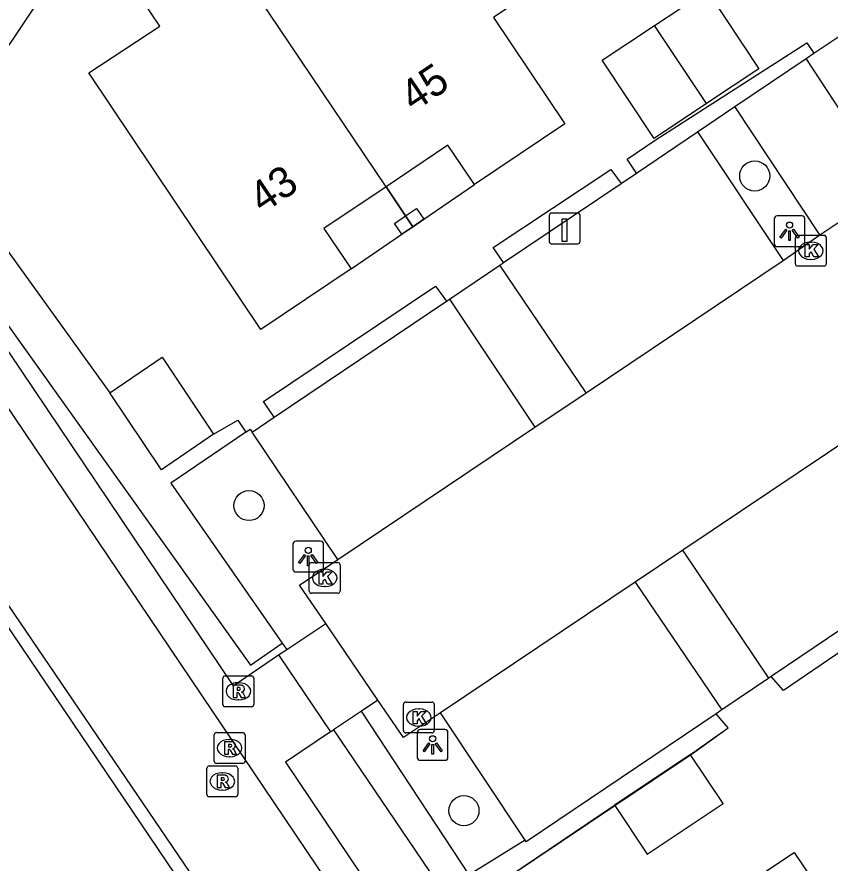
# Model space of a CAD drawing. Extents: x 158797 to 159887, y 384318 to 385255.
# Drawn here: x 158945.21 to 158971.6, y 384679.81 to 384707.27 of the extents above; entities that cross this region are included whole.
import ezdxf

# ---------------------------------------------------------------- set-up
doc = ezdxf.new("R2010")
doc.units = 0
for name, color, linetype in [('IMGEO_Berm_groen', 7, 'Continuous'), ('IMGEO_Boom', 7, 'Continuous'), ('IMGEO_Groenvoorziening', 7, 'Continuous'), ('IMGEO_Haag', 7, 'Continuous'), ('IMGEO_Kolk', 7, 'Continuous'), ('IMGEO_Laadpaal', 7, 'Continuous'), ('IMGEO_Lichtpunt', 7, 'Continuous'), ('IMGEO_Pand', 7, 'Continuous'), ('IMGEO_Pand_nummerreeks', 7, 'Continuous'), ('IMGEO_Pand_overbouw', 7, 'Continuous'), ('IMGEO_Parkeervlak_open', 7, 'Continuous'), ('IMGEO_Rijbaan_lokaal_open', 7, 'Continuous'), ('IMGEO_Rioolput', 7, 'Continuous'), ('IMGEO_Voetpad_halfverhard', 7, 'Continuous'), ('IMGEO_Voetpad_op_trap', 7, 'Continuous'), ('IMGEO_Voetpad_open', 7, 'Continuous')]:
    doc.layers.add(name, color=color, linetype=linetype)

msp = doc.modelspace()

# ---------------------------------------------------------------- linework, layer by layer
at = {"layer": 'IMGEO_Berm_groen'}
msp.add_lwpolyline([(158953.822, 384686.947), (158953.964, 384686.744)], dxfattribs=at)
at = {"layer": 'IMGEO_Boom'}
for centre in [(158969.154, 384702.11), (158952.741, 384691.413), (158959.716, 384681.512)]:
    msp.add_circle(centre, 0.489, dxfattribs=at)
at = {"layer": 'IMGEO_Groenvoorziening'}
for points in [[(158952.639, 384693.793), (158952.782, 384693.887), (158952.843, 384693.8)], [(158967.066, 384683.335), (158968.288, 384684.196)], [(158960.312, 384678.787), (158964.603, 384681.689)]]:
    msp.add_lwpolyline(points, dxfattribs=at)
at = {"layer": 'IMGEO_Haag'}
for points in [[(158966.613, 384739.202), (158965.512, 384740.522), (158941.142, 384702.551), (158952.786, 384686.235), (158953.822, 384686.947)], [(158966.078, 384738.835), (158965.491, 384739.134), (158959.225, 384729.429), (158959.613, 384729.029), (158955.43, 384722.46), (158949.45, 384713.078), (158942.598, 384702.871), (158948.229, 384695.075)], [(158965.32, 384702.204), (158965.013, 384702.659), (158965.927, 384703.267), (158970.844, 384706.429), (158971.076, 384706.091)], [(158967.298, 384703.536), (158968.504, 384704.361)], [(158961.002, 384699.296), (158960.66, 384699.787), (158964.489, 384702.315), (158964.816, 384701.864)], [(158953.553, 384694.278), (158953.207, 384694.787), (158958.791, 384698.529), (158959.147, 384698.046)], [(158951.593, 384693.727), (158952.375, 384694.187), (158952.639, 384693.793)], [(158952.639, 384693.793), (158950.206, 384692.135), (158953.822, 384686.947)], [(158977.555, 384656.193), (158970.058, 384651.22), (158941.507, 384693.215), (158927, 384683.401), (158930.702, 384677.442), (158928.077, 384675.641), (158928.67, 384674.688)], [(158982.198, 384627.503), (158986.877, 384630.783), (158991.18, 384624.297), (159005.347, 384633.805), (158997.226, 384645.658), (158986.56, 384661.35), (158977.807, 384655.577), (158970.042, 384650.292), (158941.462, 384692.581), (158927.478, 384683.208), (158931.293, 384677.308), (158928.892, 384675.59), (158929.234, 384675.051), (158928.67, 384674.688)], [(158976.326, 384689.664), (158970.085, 384685.407), (158969.689, 384685.861)], [(158961.705, 384680.553), (158959.891, 384679.427), (158956.395, 384684.743)], [(158968.288, 384684.196), (158967.901, 384684.656)], [(158955.484, 384684.134), (158959.482, 384678.23)], [(158967.07, 384683.329), (158967.131, 384683.37), (158968.288, 384684.196)], [(158964.611, 384681.677), (158967.07, 384683.329)], [(158960.312, 384678.787), (158964.611, 384681.677)]]:
    msp.add_lwpolyline(points, dxfattribs=at)
at = {"layer": 'IMGEO_Kolk'}
for p, q in [((158970.55, 384700.183), (158971.402, 384700.183)), ((158970.475, 384699.257), (158970.475, 384700.109)), ((158970.963, 384699.963), (158970.988, 384699.963)), ((158971.476, 384700.109), (158971.476, 384699.257)), ((158970.986, 384699.403), (158970.961, 384699.403)), ((158971.402, 384699.183), (158970.55, 384699.183)), ((158954.697, 384688.639), (158954.697, 384689.491)), ((158954.772, 384689.565), (158955.624, 384689.565)), ((158955.698, 384689.491), (158955.698, 384688.639)), ((158955.185, 384689.345), (158955.21, 384689.345)), ((158955.208, 384688.785), (158955.183, 384688.785)), ((158955.624, 384688.565), (158954.772, 384688.565)), ((158957.752, 384684.109), (158957.752, 384684.961)), ((158957.827, 384685.035), (158958.679, 384685.035)), ((158958.24, 384684.815), (158958.265, 384684.815)), ((158958.753, 384684.961), (158958.753, 384684.109)), ((158958.263, 384684.255), (158958.238, 384684.255)), ((158958.679, 384684.035), (158957.827, 384684.035))]:
    msp.add_line(p, q, dxfattribs=at)
for points in [[(158970.55, 384700.183), (158971.402, 384700.183)], [(158970.475, 384699.257), (158970.475, 384700.109)], [(158971.476, 384700.109), (158971.476, 384699.257)], [(158970.796, 384699.883), (158970.919, 384699.883), (158970.919, 384699.732), (158971.049, 384699.883), (158971.213, 384699.883), (158971.067, 384699.732), (158971.22, 384699.483), (158971.068, 384699.483), (158970.983, 384699.647), (158970.919, 384699.58), (158970.919, 384699.483), (158970.796, 384699.483), (158970.796, 384699.883)], [(158971.402, 384699.183), (158970.55, 384699.183)], [(158954.697, 384688.639), (158954.697, 384689.491)], [(158954.772, 384689.565), (158955.624, 384689.565)], [(158955.698, 384689.491), (158955.698, 384688.639)], [(158955.018, 384689.265), (158955.141, 384689.265), (158955.141, 384689.114), (158955.271, 384689.265), (158955.435, 384689.265), (158955.289, 384689.114), (158955.442, 384688.865), (158955.29, 384688.865), (158955.205, 384689.029), (158955.141, 384688.962), (158955.141, 384688.865), (158955.018, 384688.865), (158955.018, 384689.265)], [(158955.624, 384688.565), (158954.772, 384688.565)], [(158957.752, 384684.109), (158957.752, 384684.961)], [(158957.827, 384685.035), (158958.679, 384685.035)], [(158958.753, 384684.961), (158958.753, 384684.109)], [(158958.073, 384684.735), (158958.196, 384684.735), (158958.196, 384684.584), (158958.326, 384684.735), (158958.49, 384684.735), (158958.344, 384684.584), (158958.497, 384684.335), (158958.345, 384684.335), (158958.26, 384684.499), (158958.196, 384684.432), (158958.196, 384684.335), (158958.073, 384684.335), (158958.073, 384684.735)], [(158958.679, 384684.035), (158957.827, 384684.035)]]:
    msp.add_lwpolyline(points, dxfattribs=at)
for centre, start, end in [((158970.552, 384700.107), 91.552, 178.448), ((158970.552, 384700.107), 91.552, 178.448), ((158971.4, 384700.107), 1.552, 88.448), ((158971.4, 384700.107), 1.552, 88.448), ((158970.552, 384699.259), 181.552, 268.448), ((158970.552, 384699.259), 181.552, 268.448), ((158971.4, 384699.259), 271.552, 358.448), ((158971.4, 384699.259), 271.552, 358.448), ((158954.774, 384689.489), 91.552, 178.448), ((158954.774, 384689.489), 91.552, 178.448), ((158955.622, 384689.489), 1.552, 88.448), ((158955.622, 384689.489), 1.552, 88.448), ((158954.774, 384688.641), 181.552, 268.448), ((158954.774, 384688.641), 181.552, 268.448), ((158955.622, 384688.641), 271.552, 358.448), ((158955.622, 384688.641), 271.552, 358.448), ((158957.829, 384684.959), 91.552, 178.448), ((158957.829, 384684.959), 91.552, 178.448), ((158958.677, 384684.959), 1.552, 88.448), ((158958.677, 384684.959), 1.552, 88.448), ((158957.829, 384684.111), 181.552, 268.448), ((158957.829, 384684.111), 181.552, 268.448), ((158958.677, 384684.111), 271.552, 358.448), ((158958.677, 384684.111), 271.552, 358.448)]:
    msp.add_arc(centre, 0.0765, start, end, dxfattribs=at)
for centre, major_axis, ratio, start_param, end_param in [((158970.962, 384699.683), (-0.387, 0.002), 0.722429, 4.712389, 7.853982), ((158970.987, 384699.683), (-0.39, 0.002), 0.717154, 1.570796, 4.712389), ((158955.184, 384689.065), (-0.387, 0.002), 0.722429, 4.712389, 7.853982), ((158955.209, 384689.065), (-0.39, 0.002), 0.717154, 1.570796, 4.712389), ((158958.239, 384684.535), (-0.387, 0.002), 0.722429, 4.712389, 7.853982), ((158958.264, 384684.535), (-0.39, 0.002), 0.717154, 1.570796, 4.712389)]:
    msp.add_ellipse(centre, major_axis=major_axis, ratio=ratio, start_param=start_param, end_param=end_param, dxfattribs=at)
at = {"layer": 'IMGEO_Laadpaal'}
for p, q in [((158962.486, 384700.822), (158962.486, 384699.981)), ((158962.486, 384700.822), (158962.486, 384699.981)), ((158963.402, 384700.906), (158962.561, 384700.906)), ((158963.402, 384700.906), (158962.561, 384700.906)), ((158963.486, 384699.99), (158963.486, 384700.831)), ((158963.486, 384699.99), (158963.486, 384700.831)), ((158962.57, 384699.906), (158963.411, 384699.906)), ((158962.57, 384699.906), (158963.411, 384699.906))]:
    msp.add_line(p, q, dxfattribs=at)
msp.add_lwpolyline([(158962.901, 384700.719), (158963.061, 384700.719), (158963.061, 384699.986), (158962.901, 384699.986), (158962.901, 384700.719)], dxfattribs=at)
for centre, start, end in [((158962.564, 384700.828), 92.4484, 184.2845), ((158962.564, 384700.828), 92.4484, 184.2845), ((158963.408, 384700.828), 2.4484, 94.2845), ((158963.408, 384700.828), 2.4484, 94.2845), ((158962.564, 384699.984), 182.4484, 274.2845), ((158962.564, 384699.984), 182.4484, 274.2845), ((158963.408, 384699.984), 272.4484, 4.2845), ((158963.408, 384699.984), 272.4484, 4.2845)]:
    msp.add_arc(centre, 0.0779, start, end, dxfattribs=at)
at = {"layer": 'IMGEO_Lichtpunt'}
for p, q in [((158970.687, 384700.812), (158969.879, 384700.812)), ((158970.687, 384700.812), (158969.879, 384700.812)), ((158969.785, 384700.717), (158969.785, 384699.91)), ((158969.785, 384700.717), (158969.785, 384699.91)), ((158970.781, 384699.91), (158970.781, 384700.717)), ((158970.781, 384699.91), (158970.781, 384700.717)), ((158969.879, 384699.816), (158970.687, 384699.816)), ((158969.879, 384699.816), (158970.687, 384699.816)), ((158954.164, 384690.161), (158954.164, 384689.354)), ((158954.164, 384690.161), (158954.164, 384689.354)), ((158955.066, 384690.256), (158954.258, 384690.256)), ((158955.066, 384690.256), (158954.258, 384690.256)), ((158955.16, 384689.354), (158955.16, 384690.161)), ((158955.16, 384689.354), (158955.16, 384690.161)), ((158954.258, 384689.26), (158955.066, 384689.26)), ((158954.258, 384689.26), (158955.066, 384689.26)), ((158958.201, 384684.048), (158958.201, 384683.241)), ((158958.201, 384684.048), (158958.201, 384683.241)), ((158959.103, 384684.143), (158958.295, 384684.143)), ((158959.103, 384684.143), (158958.295, 384684.143)), ((158959.197, 384683.241), (158959.197, 384684.048)), ((158959.197, 384683.241), (158959.197, 384684.048)), ((158958.295, 384683.147), (158959.103, 384683.147)), ((158958.295, 384683.147), (158959.103, 384683.147))]:
    msp.add_line(p, q, dxfattribs=at)
for points in [[(158970.159, 384700.381), (158970.198, 384700.353), (158970.01, 384700.091), (158969.972, 384700.118), (158970.159, 384700.381)], [(158970.261, 384700.333), (158970.308, 384700.333), (158970.308, 384700.011), (158970.261, 384700.011), (158970.261, 384700.333)], [(158970.371, 384700.353), (158970.409, 384700.38), (158970.596, 384700.118), (158970.557, 384700.09), (158970.371, 384700.353)], [(158954.538, 384689.825), (158954.577, 384689.797), (158954.389, 384689.535), (158954.351, 384689.562), (158954.538, 384689.825)], [(158954.64, 384689.777), (158954.687, 384689.777), (158954.687, 384689.455), (158954.64, 384689.455), (158954.64, 384689.777)], [(158954.75, 384689.797), (158954.788, 384689.824), (158954.975, 384689.562), (158954.936, 384689.534), (158954.75, 384689.797)], [(158958.575, 384683.712), (158958.614, 384683.684), (158958.426, 384683.422), (158958.388, 384683.449), (158958.575, 384683.712)], [(158958.787, 384683.684), (158958.825, 384683.711), (158959.012, 384683.449), (158958.973, 384683.421), (158958.787, 384683.684)], [(158958.677, 384683.664), (158958.724, 384683.664), (158958.724, 384683.342), (158958.677, 384683.342), (158958.677, 384683.664)]]:
    msp.add_lwpolyline(points, dxfattribs=at)
for centre in [(158970.284, 384700.515), (158954.663, 384689.959), (158958.7, 384683.846)]:
    msp.add_circle(centre, 0.0994, dxfattribs=at)
for centre, start, end in [((158969.879, 384700.717), 90, 180), ((158969.879, 384700.717), 90, 180), ((158970.687, 384700.717), 0, 90), ((158970.687, 384700.717), 0, 90), ((158969.879, 384699.91), 180, 270), ((158969.879, 384699.91), 180, 270), ((158970.687, 384699.91), 270, 0), ((158970.687, 384699.91), 270, 360), ((158954.258, 384690.161), 90, 180), ((158954.258, 384690.161), 90, 180), ((158955.066, 384690.161), 0, 90), ((158955.066, 384690.161), 0, 90), ((158954.258, 384689.354), 180, 270), ((158954.258, 384689.354), 180, 270), ((158955.066, 384689.354), 270, 0), ((158955.066, 384689.354), 270, 360), ((158958.295, 384684.048), 90, 180), ((158958.295, 384684.048), 90, 180), ((158959.103, 384684.048), 0, 90), ((158959.103, 384684.048), 0, 90), ((158958.295, 384683.241), 180, 270), ((158958.295, 384683.241), 180, 270), ((158959.103, 384683.241), 270, 0), ((158959.103, 384683.241), 270, 360)]:
    msp.add_arc(centre, 0.0946, start, end, dxfattribs=at)
at = {"layer": 'IMGEO_Pand'}
for points in [[(158951.323, 384710.489), (158953.966, 384712.265), (158955.134, 384710.528), (158958.604, 384712.879), (158961.859, 384708.055), (158960.676, 384707.255), (158962.987, 384703.797), (158960.062, 384701.827), (158959.198, 384703.109), (158957.19, 384701.758)], [(158957.19, 384701.758), (158955.173, 384700.402), (158956.052, 384699.091), (158953.129, 384697.13), (158947.547, 384705.451), (158949.843, 384706.973), (158948.68, 384708.713), (158951.323, 384710.489)], [(158957.19, 384701.758), (158951.323, 384710.489)], [(158965.906, 384706.996), (158967.608, 384708.126), (158969.286, 384705.589), (158967.591, 384704.459)], [(158967.591, 384704.459), (158965.894, 384703.329), (158964.204, 384705.865), (158965.906, 384706.996)], [(158967.591, 384704.459), (158965.906, 384706.996)], [(158957.824, 384700.814), (158958.174, 384701.053), (158958.413, 384700.702), (158958.061, 384700.462)], [(158958.061, 384700.462), (158957.7, 384700.216), (158957.461, 384700.567), (158957.824, 384700.814)], [(158958.061, 384700.462), (158957.824, 384700.814)], [(158948.229, 384695.075), (158949.925, 384696.227), (158951.593, 384693.727)], [(158951.593, 384693.727), (158949.898, 384692.576), (158948.229, 384695.075)], [(158967.066, 384683.335), (158964.603, 384681.689)], [(158964.611, 384681.677), (158965.665, 384680.099), (158968.128, 384681.745), (158967.07, 384683.329)], [(158967.07, 384683.329), (158967.066, 384683.335)], [(158964.603, 384681.689), (158964.611, 384681.677)], [(158973.499, 384670.144), (158969.575, 384667.487), (158966.374, 384672.215), (158967.556, 384673.016), (158966.448, 384674.653), (158968.717, 384676.209), (158967.399, 384678.13), (158970.433, 384680.157), (158972.831, 384676.593)]]:
    msp.add_lwpolyline(points, dxfattribs=at)
at = {"layer": 'IMGEO_Pand_overbouw'}
for points in [[(158957.19, 384701.758), (158957.824, 384700.814), (158958.061, 384700.462), (158958.413, 384700.702), (158960.062, 384701.827), (158959.198, 384703.109)], [(158958.061, 384700.462), (158957.824, 384700.814), (158957.19, 384701.758), (158955.173, 384700.402), (158956.052, 384699.091), (158957.7, 384700.216)]]:
    msp.add_lwpolyline(points, close=True, dxfattribs=at)
at = {"layer": 'IMGEO_Parkeervlak_open'}
for points in [[(158968.504, 384704.361), (158970.818, 384705.917)], [(158971.272, 384700.198), (158968.504, 384704.361)], [(158965.32, 384702.204), (158967.298, 384703.536)], [(158967.298, 384703.536), (158970.077, 384699.361)], [(158964.816, 384701.864), (158965.32, 384702.204)], [(158961.002, 384699.296), (158964.816, 384701.864)], [(158960.884, 384699.216), (158961.002, 384699.296)], [(158953.553, 384694.278), (158959.147, 384698.046)], [(158959.147, 384698.046), (158959.251, 384698.116)], [(158952.843, 384693.8), (158953.553, 384694.278)], [(158955.626, 384689.662), (158952.843, 384693.8)], [(158976.14, 384690.213), (158969.689, 384685.861)], [(158969.689, 384685.861), (158969.61, 384685.808)], [(158961.705, 384680.553), (158958.961, 384684.691)], [(158967.901, 384684.656), (158961.741, 384680.499), (158961.705, 384680.553)], [(158968.087, 384684.781), (158967.901, 384684.656)]]:
    msp.add_lwpolyline(points, dxfattribs=at)
at = {"layer": 'IMGEO_Rijbaan_lokaal_open'}
for points in [[(158971.272, 384700.198), (158973.571, 384701.736)], [(158970.077, 384699.361), (158971.272, 384700.198)], [(158963.682, 384695.069), (158970.077, 384699.361)], [(158962.02, 384693.954), (158963.682, 384695.069)], [(158973.391, 384694.368), (158966.82, 384689.961)], [(158955.626, 384689.662), (158962.02, 384693.954)], [(158966.82, 384689.961), (158965.277, 384688.927)], [(158955.232, 384687.583), (158954.382, 384688.829), (158955.626, 384689.662)], [(158965.277, 384688.927), (158958.961, 384684.691)], [(158956.927, 384685.098), (158955.232, 384687.583)], [(158958.961, 384684.691), (158957.755, 384683.883), (158956.927, 384685.098)]]:
    msp.add_lwpolyline(points, dxfattribs=at)
at = {"layer": 'IMGEO_Rioolput'}
for p, q in [((158951.895, 384684.959), (158951.895, 384685.811)), ((158951.97, 384685.885), (158952.822, 384685.885)), ((158952.383, 384685.665), (158952.408, 384685.665)), ((158952.896, 384685.811), (158952.896, 384684.959)), ((158952.406, 384685.105), (158952.381, 384685.105)), ((158952.822, 384684.885), (158951.97, 384684.885)), ((158951.685, 384684.044), (158952.537, 384684.044)), ((158951.61, 384683.118), (158951.61, 384683.97)), ((158952.098, 384683.824), (158952.123, 384683.824)), ((158952.611, 384683.97), (158952.611, 384683.118)), ((158952.121, 384683.264), (158952.096, 384683.264)), ((158951.374, 384682.036), (158951.374, 384682.888)), ((158951.449, 384682.962), (158952.301, 384682.962)), ((158952.537, 384683.044), (158951.685, 384683.044)), ((158952.375, 384682.888), (158952.375, 384682.036)), ((158951.862, 384682.742), (158951.887, 384682.742)), ((158951.885, 384682.182), (158951.86, 384682.182)), ((158952.301, 384681.962), (158951.449, 384681.962))]:
    msp.add_line(p, q, dxfattribs=at)
for points in [[(158951.895, 384684.959), (158951.895, 384685.811)], [(158951.97, 384685.885), (158952.822, 384685.885)], [(158952.896, 384685.811), (158952.896, 384684.959)], [(158952.484, 384685.583), (158952.232, 384685.585), (158952.232, 384685.185)], [(158952.232, 384685.185), (158952.356, 384685.185), (158952.356, 384685.347), (158952.367, 384685.347)], [(158952.41, 384685.504), (158952.356, 384685.504), (158952.356, 384685.423)], [(158952.356, 384685.423), (158952.408, 384685.423)], [(158952.414, 384685.318), (158952.485, 384685.185), (158952.625, 384685.185), (158952.56, 384685.311)], [(158952.822, 384684.885), (158951.97, 384684.885)], [(158951.685, 384684.044), (158952.537, 384684.044)], [(158951.61, 384683.118), (158951.61, 384683.97)], [(158952.199, 384683.742), (158951.947, 384683.744), (158951.947, 384683.344)], [(158952.611, 384683.97), (158952.611, 384683.118)], [(158951.947, 384683.344), (158952.071, 384683.344), (158952.071, 384683.506), (158952.082, 384683.506)], [(158952.125, 384683.663), (158952.071, 384683.663), (158952.071, 384683.582)], [(158952.071, 384683.582), (158952.123, 384683.582)], [(158952.129, 384683.477), (158952.2, 384683.344), (158952.34, 384683.344), (158952.275, 384683.47)], [(158951.374, 384682.036), (158951.374, 384682.888)], [(158951.449, 384682.962), (158952.301, 384682.962)], [(158952.537, 384683.044), (158951.685, 384683.044)], [(158952.375, 384682.888), (158952.375, 384682.036)], [(158951.963, 384682.66), (158951.711, 384682.662), (158951.711, 384682.262)], [(158951.711, 384682.262), (158951.835, 384682.262), (158951.835, 384682.424), (158951.846, 384682.424)], [(158951.889, 384682.581), (158951.835, 384682.581), (158951.835, 384682.5)], [(158951.835, 384682.5), (158951.887, 384682.5)], [(158951.893, 384682.395), (158951.964, 384682.262), (158952.104, 384682.262), (158952.039, 384682.388)], [(158952.301, 384681.962), (158951.449, 384681.962)]]:
    msp.add_lwpolyline(points, dxfattribs=at)
for centre, radius, start, end in [((158951.972, 384685.809), 0.0765, 91.552, 178.448), ((158951.972, 384685.809), 0.0765, 91.552, 178.448), ((158952.82, 384685.809), 0.0765, 1.552, 88.448), ((158952.82, 384685.809), 0.0765, 1.552, 88.448), ((158952.366, 384685.294), 0.0533, 26.0293, 88.6989), ((158952.392, 384685.612), 0.19, 274.7715, 282.9687), ((158952.416, 384685.408), 0.0964, 77.0061, 93.1865), ((158952.43, 384685.465), 0.0378, 276.6634, 79.6772), ((158952.483, 384685.473), 0.109, 350.3612, 89.416), ((158952.481, 384685.473), 0.112, 277.5842, 350.9817), ((158952.465, 384685.258), 0.108, 29.5134, 73.7905), ((158951.972, 384684.961), 0.0765, 181.552, 268.448), ((158951.972, 384684.961), 0.0765, 181.552, 268.448), ((158952.82, 384684.961), 0.0765, 271.552, 358.448), ((158952.82, 384684.961), 0.0765, 271.552, 358.448), ((158951.687, 384683.968), 0.0765, 91.552, 178.448), ((158951.687, 384683.968), 0.0765, 91.552, 178.448), ((158952.535, 384683.968), 0.0765, 1.552, 88.448), ((158952.535, 384683.968), 0.0765, 1.552, 88.448), ((158952.198, 384683.632), 0.109, 350.3612, 89.416), ((158952.081, 384683.453), 0.0533, 26.0293, 88.6989), ((158952.107, 384683.771), 0.19, 274.7715, 282.9687), ((158952.131, 384683.567), 0.0964, 77.0061, 93.1865), ((158952.145, 384683.624), 0.0378, 276.6634, 79.6772), ((158952.196, 384683.632), 0.112, 277.5842, 350.9817), ((158952.18, 384683.417), 0.108, 29.5134, 73.7905), ((158951.451, 384682.886), 0.0765, 91.552, 178.448), ((158951.451, 384682.886), 0.0765, 91.552, 178.448), ((158951.687, 384683.12), 0.0765, 181.552, 268.448), ((158951.687, 384683.12), 0.0765, 181.552, 268.448), ((158952.299, 384682.886), 0.0765, 1.552, 88.448), ((158952.299, 384682.886), 0.0765, 1.552, 88.448), ((158952.535, 384683.12), 0.0765, 271.552, 358.448), ((158952.535, 384683.12), 0.0765, 271.552, 358.448), ((158951.962, 384682.55), 0.109, 350.3612, 89.416), ((158951.845, 384682.371), 0.0533, 26.0293, 88.6989), ((158951.871, 384682.689), 0.19, 274.7715, 282.9687), ((158951.895, 384682.485), 0.0964, 77.0061, 93.1865), ((158951.909, 384682.542), 0.0378, 276.6634, 79.6772), ((158951.96, 384682.55), 0.112, 277.5842, 350.9817), ((158951.944, 384682.335), 0.108, 29.5134, 73.7905), ((158951.451, 384682.038), 0.0765, 181.552, 268.448), ((158951.451, 384682.038), 0.0765, 181.552, 268.448), ((158952.299, 384682.038), 0.0765, 271.552, 358.448), ((158952.299, 384682.038), 0.0765, 271.552, 358.448)]:
    msp.add_arc(centre, radius, start, end, dxfattribs=at)
for centre, major_axis, ratio, start_param, end_param in [((158952.382, 384685.385), (-0.387, 0.002), 0.722429, 4.712389, 7.853982), ((158952.407, 384685.385), (-0.39, 0.002), 0.717154, 1.570796, 4.712389), ((158952.097, 384683.544), (-0.387, 0.002), 0.722429, 4.712389, 7.853982), ((158952.122, 384683.544), (-0.39, 0.002), 0.717154, 1.570796, 4.712389), ((158951.861, 384682.462), (-0.387, 0.002), 0.722429, 4.712389, 7.853982), ((158951.886, 384682.462), (-0.39, 0.002), 0.717154, 1.570796, 4.712389)]:
    msp.add_ellipse(centre, major_axis=major_axis, ratio=ratio, start_param=start_param, end_param=end_param, dxfattribs=at)
at = {"layer": 'IMGEO_Voetpad_halfverhard'}
for points in [[(158938.197, 384703.116), (158942.084, 384700.551), (158942.526, 384699.967), (158952.229, 384685.559), (158953.693, 384686.565)], [(158977.555, 384656.193), (158975.853, 384658.793), (158971.165, 384655.643), (158941.388, 384699.818), (158939.315, 384701.171), (158937.66, 384698.642), (158936.004, 384699.719)], [(158953.693, 384686.565), (158955.391, 384684.072)], [(158955.391, 384684.072), (158953.921, 384683.081), (158971.449, 384657.024), (158988.039, 384668.203), (158987.037, 384669.652), (158988.632, 384670.744)]]:
    msp.add_lwpolyline(points, dxfattribs=at)
at = {"layer": 'IMGEO_Voetpad_op_trap'}
for points in [[(158953.964, 384686.744), (158955.232, 384687.583)], [(158953.693, 384686.565), (158953.964, 384686.744)], [(158956.927, 384685.098), (158956.395, 384684.743)], [(158956.395, 384684.743), (158955.484, 384684.134)], [(158955.391, 384684.072), (158955.484, 384684.134)]]:
    msp.add_lwpolyline(points, dxfattribs=at)
at = {"layer": 'IMGEO_Voetpad_open'}
for points in [[(158971.076, 384706.091), (158972.017, 384706.723)], [(158970.818, 384705.917), (158971.076, 384706.091)], [(158973.571, 384701.736), (158970.818, 384705.917)], [(158959.251, 384698.116), (158960.884, 384699.216)], [(158963.682, 384695.069), (158960.884, 384699.216)], [(158959.251, 384698.116), (158962.02, 384693.954)], [(158969.61, 384685.808), (158966.82, 384689.961)], [(158965.277, 384688.927), (158968.087, 384684.781)], [(158969.61, 384685.808), (158968.087, 384684.781)]]:
    msp.add_lwpolyline(points, dxfattribs=at)

# ---------------------------------------------------------------- texts
at = {"layer": 'IMGEO_Pand_nummerreeks'}
for s, p in [('45', (158958.082, 384704.166)), ('43', (158953.179, 384700.868))]:
    msp.add_text(s, height=1, rotation=33.9248, dxfattribs=at).set_placement(p)

doc.saveas('drawing.dxf')
